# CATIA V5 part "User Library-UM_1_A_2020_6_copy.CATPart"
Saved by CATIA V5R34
Part number: 7D37CFB8-28AF-4AE6-9052-58D53263B79B
Revision: ANY
Definition: UNKNOWN
Nomenclature: 7D37CFB8-28AF-4AE6-9052-58D53263B79B
Source: Unknown
Bounding box of the stored display mesh (mm): x 34.376 to 54.376, y 70.124 to 90.124, z 0 to 350
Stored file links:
  C:\Users\Apolinar\Desktop\cnc\User Library-UM_1_A_2020_6_copy.CATPart
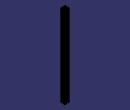
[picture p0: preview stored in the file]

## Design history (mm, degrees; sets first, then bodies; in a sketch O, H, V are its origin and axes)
Set1
  Sketch1 on face of Solid1, origin (54.3765, 0, 0), H (0, 1, 0), V (0, 0, 1)
    line L1 (70.1241, 1000) -> (90.1241, 1000)
    line L2 (90.1241, 1000) -> (90.1241, 350)
    line L3 (90.1241, 350) -> (70.1241, 350)
    line L4 (70.1241, 350) -> (70.1241, 1000)
    reference projected line E1 (90.1241, 1000) -> (90.1241, 0) from edge [face of Solid1 | face of Solid1]
    reference projected line E2 (70.1241, 1000) -> (70.1241, 0) from edge [face of Solid1 | face of Solid1]
    reference projected point E3 (83.8741, 1000) from vertex [face of Solid1 | face of Solid1 | face of Solid1]
    distance L3 H = 350
    horizontal: L1 H, L3 H
    vertical: L2 V, L4 V
    coincidence: E1 L2, E2 L4, L1 E3
Body1 "NONE" (main body)
  Solid1: solid without history
  Pocket1: profile Sketch1, direction (-1, 0, 0), length 20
